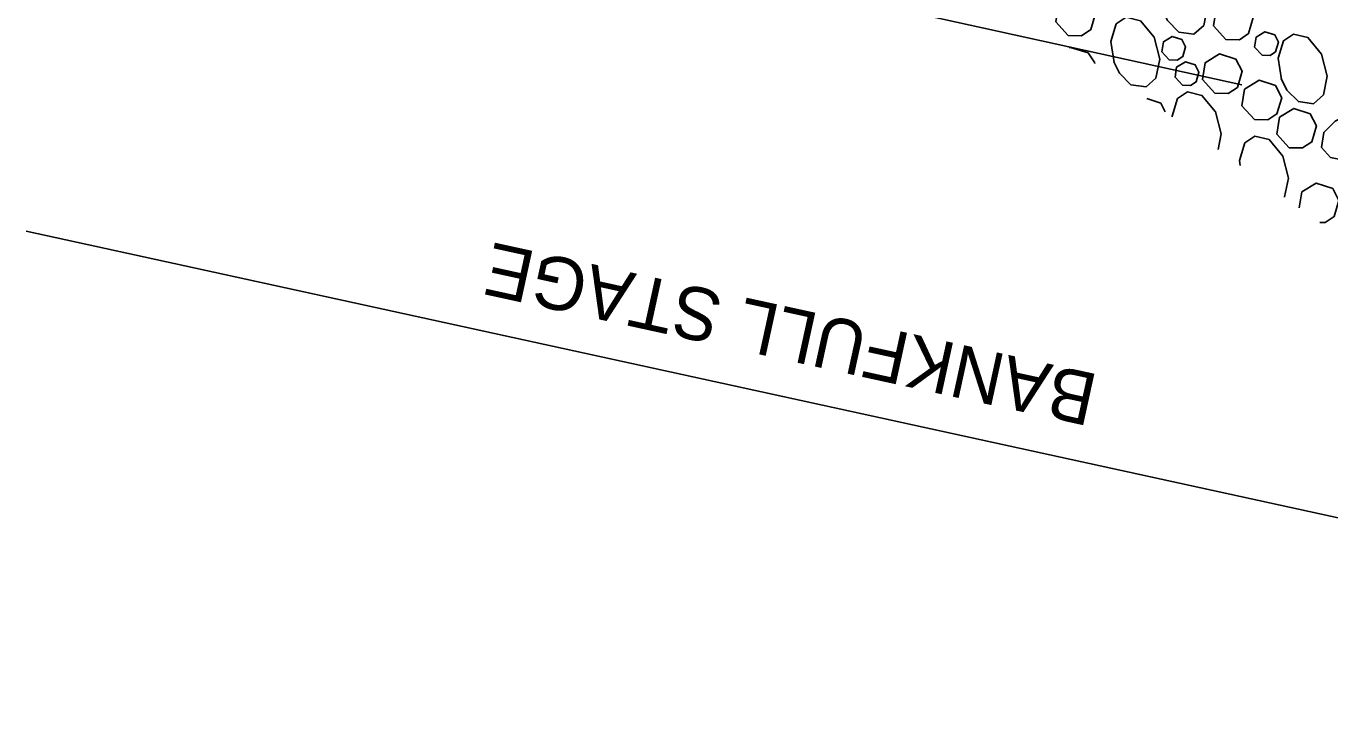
# Model space of a CAD drawing. Extents: x 2126110 to 2128246, y 1804858 to 1811658.
# Drawn here: x 2126177.7 to 2126672.7, y 1808883.8 to 1809146 of the extents above; entities that cross this region are included whole.
import ezdxf

# ---------------------------------------------------------------- set-up
doc = ezdxf.new("R2010")
doc.units = 0
for name, color, linetype in [('1', 7, 'Continuous'), ('DET-EARTH', 7, 'Continuous'), ('Old_Level_1', 7, 'Continuous')]:
    doc.layers.add(name, color=color, linetype=linetype)

msp = doc.modelspace()

# ---------------------------------------------------------------- linework, layer by layer
at = {"layer": '1'}
msp.add_line((2126639.29, 1809123.78), (2126180.41, 1809224.52), dxfattribs=at)
at = {"layer": 'DET-EARTH'}
msp.add_line((2127021.5, 1808883.82), (2126177.68, 1809068.21), dxfattribs=at)
at = {"layer": 'Old_Level_1'}
for points in [[(2126608.94, 1809152.16), (2126607.63, 1809160.18), (2126609.69, 1809166.82), (2126613.45, 1809169.37), (2126618.93, 1809168.07), (2126624.11, 1809161.82), (2126626.23, 1809153.44), (2126624.8, 1809146.3), (2126621.08, 1809142.92), (2126615.33, 1809143.78), (2126610.97, 1809148.13), (2126608.81, 1809152.5)], [(2126573.34, 1809142.49), (2126568.59, 1809147.65), (2126569.61, 1809154.02), (2126575.1, 1809157.41), (2126581.32, 1809155.39), (2126583.7, 1809150.79), (2126581.9, 1809144.68), (2126578.42, 1809142.38), (2126573.34, 1809142.49)], [(2126633.21, 1809140.96), (2126628.47, 1809146.13), (2126629.49, 1809152.5), (2126634.98, 1809155.88), (2126641.19, 1809153.86), (2126643.58, 1809149.27), (2126641.77, 1809143.15), (2126638.3, 1809140.85), (2126633.22, 1809140.97)], [(2126590.77, 1809132.17), (2126589.46, 1809140.18), (2126591.53, 1809146.83), (2126595.29, 1809149.38), (2126600.76, 1809148.07), (2126605.94, 1809141.82), (2126608.06, 1809133.45), (2126606.63, 1809126.31), (2126602.91, 1809122.92), (2126597.16, 1809123.78), (2126592.8, 1809128.14), (2126590.65, 1809132.51)], [(2126611.68, 1809133.16), (2126608.83, 1809136.26), (2126609.44, 1809140.08), (2126612.74, 1809142.11), (2126616.47, 1809140.9), (2126617.9, 1809138.14), (2126616.81, 1809134.47), (2126614.73, 1809133.09), (2126611.68, 1809133.16)], [(2126646.92, 1809134.95), (2126644.08, 1809138.05), (2126644.69, 1809141.87), (2126647.98, 1809143.9), (2126651.71, 1809142.68), (2126653.14, 1809139.93), (2126652.06, 1809136.26), (2126649.97, 1809134.88), (2126646.93, 1809134.95)], [(2126654.33, 1809125.78), (2126653.02, 1809133.79), (2126655.09, 1809140.43), (2126658.85, 1809142.98), (2126664.32, 1809141.68), (2126669.5, 1809135.43), (2126671.62, 1809127.05), (2126670.19, 1809119.91), (2126666.47, 1809116.53), (2126660.72, 1809117.39), (2126656.37, 1809121.74), (2126654.21, 1809126.12)], [(2126573.63, 1809137.84), (2126574.23, 1809137.94), (2126580.87, 1809135.87), (2126583.42, 1809132.11), (2126583.36, 1809131.86)], [(2126629, 1809120.58), (2126624.26, 1809125.75), (2126625.27, 1809132.12), (2126630.76, 1809135.5), (2126636.98, 1809133.48), (2126639.37, 1809128.89), (2126637.56, 1809122.77), (2126634.08, 1809120.47), (2126629.01, 1809120.59)], [(2126616.74, 1809123.54), (2126613.89, 1809126.64), (2126614.5, 1809130.46), (2126617.8, 1809132.49), (2126621.53, 1809131.28), (2126622.96, 1809128.52), (2126621.87, 1809124.85), (2126619.79, 1809123.47), (2126616.74, 1809123.54)], [(2126644.01, 1809110.53), (2126639.26, 1809115.7), (2126640.27, 1809122.07), (2126645.77, 1809125.45), (2126651.98, 1809123.43), (2126654.37, 1809118.84), (2126652.56, 1809112.72), (2126649.08, 1809110.42), (2126644.01, 1809110.53)], [(2126612.84, 1809111.61), (2126612.8, 1809111.84), (2126614.86, 1809118.49), (2126618.63, 1809121.04), (2126624.1, 1809119.73), (2126629.28, 1809113.48), (2126631.4, 1809105.11), (2126630.21, 1809099.16)], [(2126603.16, 1809118.55), (2126608.45, 1809116.82), (2126610.16, 1809113.53)], [(2126657.22, 1809099.88), (2126652.47, 1809105.04), (2126653.48, 1809111.41), (2126658.98, 1809114.8), (2126665.19, 1809112.77), (2126667.58, 1809108.18), (2126665.77, 1809102.07), (2126662.29, 1809099.76), (2126657.22, 1809099.88)], [(2126678.75, 1809112.03), (2126686.76, 1809113.35), (2126693.41, 1809111.28), (2126695.96, 1809107.52), (2126694.66, 1809102.05), (2126688.41, 1809096.87), (2126680.03, 1809094.75), (2126672.89, 1809096.17), (2126669.51, 1809099.89), (2126670.37, 1809105.65), (2126674.72, 1809110), (2126679.09, 1809112.16)], [(2126638.62, 1809093.14), (2126638.31, 1809095.04), (2126640.37, 1809101.68), (2126644.14, 1809104.23), (2126649.61, 1809102.93), (2126654.79, 1809096.68), (2126656.91, 1809088.31), (2126655.48, 1809081.16), (2126655.42, 1809081.11)], [(2126661.07, 1809077.06), (2126662.03, 1809083.07), (2126667.52, 1809086.45), (2126673.74, 1809084.43), (2126676.12, 1809079.84), (2126674.31, 1809073.72), (2126670.84, 1809071.42), (2126668.88, 1809071.47)]]:
    msp.add_lwpolyline(points, dxfattribs=at)

# ---------------------------------------------------------------- texts
at = {"layer": 'DET-EARTH'}
msp.add_text('BANKFULL STAGE', height=20, rotation=167.6736, dxfattribs=at).set_placement((2126585.41, 1809013.62))

doc.saveas('drawing.dxf')
